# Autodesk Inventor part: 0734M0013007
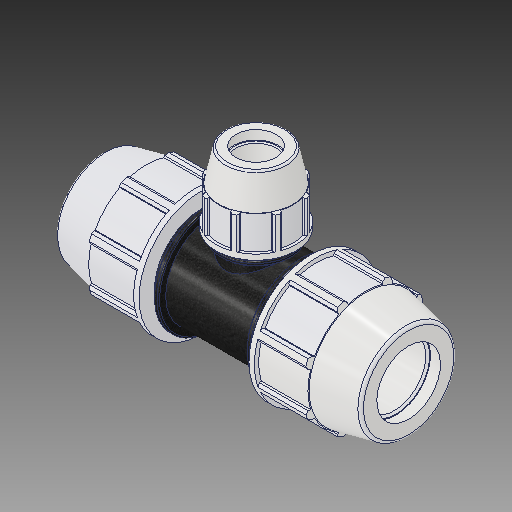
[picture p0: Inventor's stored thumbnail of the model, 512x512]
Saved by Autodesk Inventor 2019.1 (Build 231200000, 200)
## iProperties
Created: 2017-02
Part Number: 0734M0013007
Material: PVC-Piping
Description: PLASSON REDUCING TEE 1 1/4'' - 3/4'' - 1 1/4''
Document SubType Name: Modeling
Designer: KIM
Mass: 92.6774 g
Surface Area: 199.44 cm^2
Volume: 66.1981 cm^3
Density: 1.4 g/cm^3
Appearance: PTFE
Author: Кирилл
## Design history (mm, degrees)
derived "0734M0.ipt"
feature "Solid1::0734M0.ipt"
feature "Solid2::0734M0.ipt"
tag "TaggingFeature1"
body "Solid1"
other parameters: "d2" = 42.1, "d4" = 8.41375, "d5" = 28.2702, "d7" = 82.042, "d11" = 3.3655, "d13" = 120 deg, "d14" = 63.15, "d15" = 12 deg, "d16" = 71.37654, "d18" = 2.105, "d19" = 35 deg, "d20" = 17.5 deg, "d21" = 76.29906, "d23" = 0, "d25" = 360 deg, "d27" = 1.64084, "d33" = 0.842, "d42" = 36.3474, "d43" = 2.46126, "d46" = 1.263, "d67" = 61.5315, "d76" = 26.6, "d77" = 53.086, "d78" = 12 deg, "d79" = 85.09, "d80" = 120 deg, "d81" = 39.9, "d82" = 7.09083, "d87" = 2.83633, "d89" = 21.2725, "d90" = 25.527, "d96" = 16.8275, "d98" = 49.36998, "d99" = 35 deg, "d100" = 17.5 deg, "d102" = 0, "d103" = 1.06172, "d107" = 360 deg, "d109" = 0.798, "d112" = 1.33, "d113" = 3.53907, "d114" = 0, "d117" = 201.93, "d118" = 46.18482, "d126" = 37.89, "d127" = 82.042, "d131" = 3.4036, "d132" = 23.94, "d133" = 59.944, "d135" = 0, "d138" = 4.0386, "d143" = 0, "d148" = 39.8145, "d168" = 37.89, "d170" = 0, "d171" = 26.6, "d173" = 0, "d176" = 3.53907, "d177" = 0, "d_" = 42.1, "E_" = 82.042, "A_" = 85.09, "l_" = 82.042, "E_1" = 53.086, "l_1" = 59.944, "d_1" = 26.6, "H_" = 201.93
